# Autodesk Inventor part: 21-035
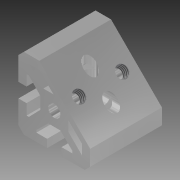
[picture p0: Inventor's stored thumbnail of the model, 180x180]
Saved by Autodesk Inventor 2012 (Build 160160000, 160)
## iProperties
Created: 2004-10
Part Number: 21-035
Material: Aluminum-6061
Document SubType Name: Modeling
Designer: Autodesk, Inc.
Manufacturer: Standard
Standards Organization: Custom
Description: CORNER ELEMENT 1, 40
Catalog Web Link: http://www.parker.com/ead/cm1.asp?cmid=809
Vendor: PARKER IPS
Mass: 78.2567 g
Surface Area: 142.922 cm^2
Volume: 28.877 cm^3
Density: 2.71 g/cm^3
CAGE: 1LJX3
Dept. ID: Product Design
Description #2: ---
Finish #1: ---
Finish #2: ---
Material ID: ---
Project Number: ---
Author: Autodesk, Inc.
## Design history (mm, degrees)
sketch "Sketch1"
  geometry: L1 (-8.333, 20)-(20, -8.333) reference; L2 (20, -8.333)-(20, -17) reference; L3 (20, -17)-(17, -20) reference; L4 (17, -20)-(4, -20) reference; L5 (4, -20)-(4, -15.5) reference; L6 (4, -15.5)-(10, -15.5) reference; L7 (10, -15.5)-(10, -14.177) reference; L8 (10, -14.177)-(3.374, -7.75) reference; L9 (3.374, -7.75)-(-3.374, -7.75) reference; L10 (-3.374, -7.75)-(-10, -14.177) reference; L11 (-10, -14.177)-(-10, -15.5) reference; L12 (-10, -15.5)-(-4, -15.5) reference; L13 (-4, -15.5)-(-4, -20) reference; L14 (-4, -20)-(-17, -20) reference; L15 (-17, -20)-(-20, -17) reference; L16 (-20, -17)-(-20, -4) reference; L17 (-20, -4)-(-15.5, -4) reference; L18 (-15.5, -4)-(-15.5, -10) reference; L19 (-15.5, -10)-(-14.177, -10) reference; L20 (-14.177, -10)-(-7.75, -3.374) reference; L21 (-7.75, -3.374)-(-7.75, 3.374) reference; L22 (-7.75, 3.374)-(-14.177, 10) reference; L23 (-14.177, 10)-(-15.5, 10) reference; L24 (-15.5, 10)-(-15.5, 4) reference; L25 (-15.5, 4)-(-20, 4) reference; L26 (-20, 4)-(-20, 17) reference; L27 (-20, 17)-(-17, 20) reference; L28 (-17, 20)-(-8.333, 20) reference; L29 (-6.124, 7.75)-(-13.874, 15.5) reference; L30 (-13.874, 15.5)-(-8.217, 15.5) reference; L31 (-8.217, 15.5)-(-0.467, 7.75) reference; L32 (-0.467, 7.75)-(-6.124, 7.75) reference; L33 (7.75, -6.124)-(15.5, -13.874) reference; L34 (15.5, -13.874)-(15.5, -8.217) reference; L35 (15.5, -8.217)-(7.75, -0.467) reference; L36 (7.75, -0.467)-(7.75, -6.124) reference; C1 r 3.4 at (0, 0) reference; 1 further point
  constraints: 72 end point, 12 horizontal, 12 vertical, 1 centre point, 51 other
extrude "Extrusion1" new body sketch "Sketch1" taper "d1" = 0 deg; stored distance "Length" = 40
sketch "Sketch2"
  geometry: L1 (0, -40)-(6.748, -40) reference; 2 further points
  constraints: 1 midpoint, 1 vertical alignment
  dimensions: "d2" = 20 distance from line of point (3.374, -20) L1
hole "Access Hole" sketch "Sketch2" at (3.374, -20) diameter "d3" = 7; stored, may be unused: countersink angle "d7" = 90 deg, drill point angle "d9" = 118 deg; dims "d4" = 6, "d5" = 4, "d6" = 2, "d8" = 8
pattern_circular "Access Hole Pattern" dims angle "d12" = 90 deg
mirror "Access Hole Mirrir"
node "Hole Terminal"
sketch "Sketch3"
  geometry: L1 (40.069, 40)-(0, 40) reference; 2 further points
  constraints: 1 midpoint, 1 vertical alignment
  dimensions: "d13" = 8 distance from line of point (20.034, 32) L1
hole "Mounting Hole" sketch "Sketch3" at (20.034, 32) diameter "d14" = 6.647; stored, may be unused: countersink angle "d18" = 90 deg, drill point angle "d20" = 0 deg; dims "d15" = 6, "d16" = 4, "d17" = 2, "d19" = 8
mirror "Mount Hole Mirror"
sketch "Sketch4"
  geometry: L1 (-4.243, 0)-(0, 0) reference; 2 further points
  constraints: 1 midpoint, 1 vertical alignment
  dimensions: "d21" = 20 distance from line of point (-2.121, 20) L1
hole "M8 Hole" sketch "Sketch4" at (-2.121, 20) diameter "d22" = 9; stored, may be unused: countersink angle "d26" = 90 deg, drill point angle "d28" = 0 deg; dims "d23" = 6, "d24" = 15, "d25" = 23, "d27" = 8
mirror "M8 Hole Mirror"
body "Solid1"
